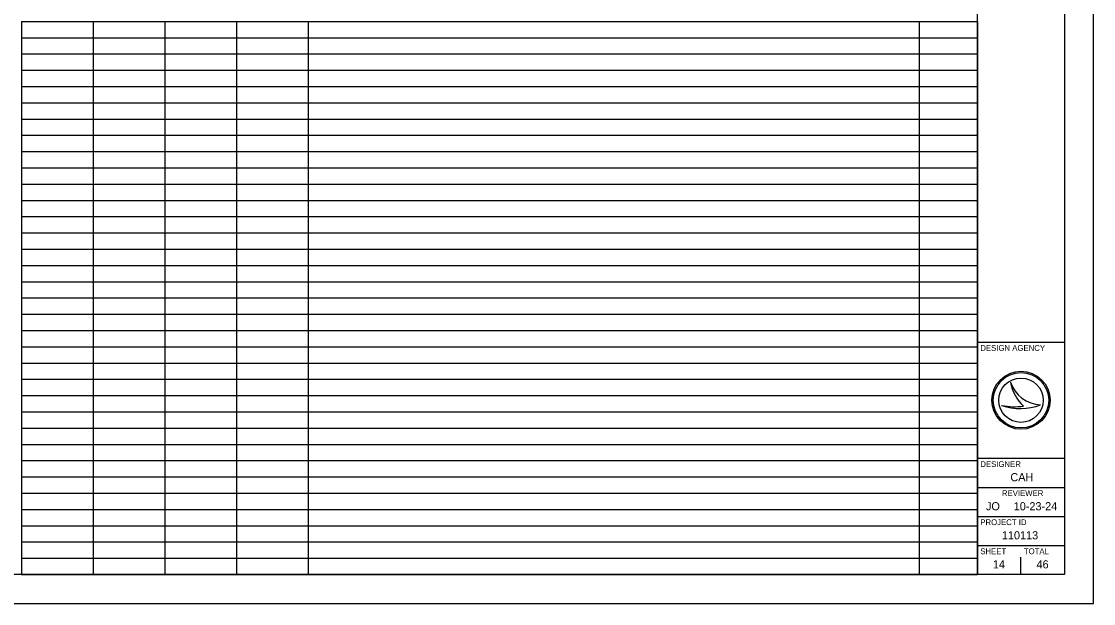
# Model space of a CAD drawing. Extents: x 0 to 34, y 0 to 22.
# Drawn here: x 15.54 to 34, y 0 to 10.02 of the extents above; entities that cross this region are included whole.
import ezdxf

# ---------------------------------------------------------------- set-up
doc = ezdxf.new("R2010")
doc.units = 0
for name, color, linetype in [('SH_Border', 7, 'Continuous'), ('SH_Cut_Line', 7, 'Continuous'), ('SH_Data', 7, 'Continuous'), ('SH_Text', 7, 'Continuous')]:
    doc.layers.add(name, color=color, linetype=linetype)

msp = doc.modelspace()

# ---------------------------------------------------------------- linework, layer by layer
at = {"layer": 'SH_Border'}
for p, q in [((32, 0.5), (32, 21.5)), ((32, 4.5), (33.5, 4.5)), ((32, 2.5), (33.5, 2.5)), ((32, 2), (33.5, 2)), ((32, 1.5), (33.5, 1.5)), ((32, 1), (33.5, 1))]:
    msp.add_line(p, q, dxfattribs=at)
msp.add_lwpolyline([(1.5, 21.5), (33.5, 21.5), (33.5, 0.5), (1.5, 0.5)], close=True, dxfattribs=at)
at = {"layer": 'SH_Cut_Line'}
msp.add_lwpolyline([(0, 0), (34, 0), (34, 22), (0, 22)], close=True, dxfattribs=at)
at = {"layer": 'SH_Data'}
for p, q in [((32.567, 3.81), (32.567, 3.81)), ((32.417, 3.41), (32.417, 3.41)), ((32.75, 3.5), (32.75, 3.5)), ((33.087, 3.419), (33.087, 3.419)), ((32.75, 0.5), (32.75, 0.8)), ((32.375, 0.675), (32.375, 0.675))]:
    msp.add_line(p, q, dxfattribs=at)
for radius in [0.5, 0.477, 0.477, 0.382]:
    msp.add_circle((32.75, 3.5), radius, dxfattribs=at)
for centre, radius, start, end in [((33.116, 3.998), 0.58, 198.9257, 198.9319), ((33.347, 3.97), 0.796, 191.6379, 191.6421), ((33.116, 3.998), 0.58, 198.9319, 267.1657), ((33.347, 3.97), 0.796, 191.6421, 226.0947), ((32.739, 4.37), 1.013, 251.4576, 290.0832), ((32.648, 4.654), 1.266, 259.4964, 259.4995), ((32.739, 4.37), 1.013, 251.4527, 251.4576), ((32.648, 4.654), 1.266, 259.4995, 276.6672)]:
    msp.add_arc(centre, radius, start, end, dxfattribs=at)
at = {"layer": 'SH_Text'}
for p, q in [((15.535, 10.02), (18.003, 10.02)), ((15.535, 10.02), (15.535, 9.74)), ((16.769, 10.02), (16.769, 9.74)), ((18.003, 10.02), (19.237, 10.02)), ((18.003, 10.02), (18.003, 9.74)), ((19.237, 10.02), (32, 10.02)), ((19.237, 10.02), (19.237, 9.74)), ((20.471, 10.02), (20.471, 9.74)), ((30.997, 10.02), (30.997, 9.74)), ((32, 10.02), (32, 9.74)), ((15.535, 9.74), (18.003, 9.74)), ((15.535, 9.74), (15.535, 8.9)), ((16.769, 9.74), (16.769, 8.9)), ((18.003, 9.74), (19.237, 9.74)), ((18.003, 9.74), (18.003, 8.9)), ((19.237, 9.74), (32, 9.74)), ((19.237, 9.74), (19.237, 8.9)), ((20.471, 9.74), (20.471, 8.9)), ((30.997, 9.74), (30.997, 8.9)), ((32, 9.74), (32, 8.9)), ((15.535, 9.46), (18.003, 9.46)), ((18.003, 9.46), (19.237, 9.46)), ((19.237, 9.46), (32, 9.46)), ((15.535, 9.18), (18.003, 9.18)), ((18.003, 9.18), (19.237, 9.18)), ((19.237, 9.18), (32, 9.18)), ((15.535, 8.9), (18.003, 8.9)), ((15.535, 8.9), (15.535, 8.34)), ((16.769, 8.9), (16.769, 8.34)), ((18.003, 8.9), (19.237, 8.9)), ((18.003, 8.9), (18.003, 8.34)), ((19.237, 8.9), (32, 8.9)), ((19.237, 8.9), (19.237, 8.34)), ((20.471, 8.9), (20.471, 8.34)), ((30.997, 8.9), (30.997, 8.34)), ((32, 8.9), (32, 8.34)), ((15.535, 8.62), (18.003, 8.62)), ((18.003, 8.62), (19.237, 8.62)), ((19.237, 8.62), (32, 8.62)), ((15.535, 8.34), (18.003, 8.34)), ((15.535, 8.34), (15.535, 7.5)), ((16.769, 8.34), (16.769, 7.5)), ((18.003, 8.34), (19.237, 8.34)), ((18.003, 8.34), (18.003, 7.5)), ((19.237, 8.34), (32, 8.34)), ((19.237, 8.34), (19.237, 7.5)), ((20.471, 8.34), (20.471, 7.5)), ((30.997, 8.34), (30.997, 7.5)), ((32, 8.34), (32, 7.5)), ((15.535, 8.06), (18.003, 8.06)), ((18.003, 8.06), (19.237, 8.06)), ((19.237, 8.06), (32, 8.06)), ((15.535, 7.78), (18.003, 7.78)), ((18.003, 7.78), (19.237, 7.78)), ((19.237, 7.78), (32, 7.78)), ((15.535, 7.5), (18.003, 7.5)), ((15.535, 7.5), (15.535, 6.94)), ((16.769, 7.5), (16.769, 6.94)), ((18.003, 7.5), (19.237, 7.5)), ((18.003, 7.5), (18.003, 6.94)), ((19.237, 7.5), (32, 7.5)), ((19.237, 7.5), (19.237, 6.94)), ((20.471, 7.5), (20.471, 6.94)), ((30.997, 7.5), (30.997, 6.94)), ((32, 7.5), (32, 6.94)), ((15.535, 7.22), (18.003, 7.22)), ((18.003, 7.22), (19.237, 7.22)), ((19.237, 7.22), (32, 7.22)), ((15.535, 6.94), (18.003, 6.94)), ((15.535, 6.94), (15.535, 6.1)), ((16.769, 6.94), (16.769, 6.1)), ((18.003, 6.94), (19.237, 6.94)), ((18.003, 6.94), (18.003, 6.1)), ((19.237, 6.94), (32, 6.94)), ((19.237, 6.94), (19.237, 6.1)), ((20.471, 6.94), (20.471, 6.1)), ((30.997, 6.94), (30.997, 6.1)), ((32, 6.94), (32, 6.1)), ((15.535, 6.66), (18.003, 6.66)), ((18.003, 6.66), (19.237, 6.66)), ((19.237, 6.66), (32, 6.66)), ((15.535, 6.38), (18.003, 6.38)), ((18.003, 6.38), (19.237, 6.38)), ((19.237, 6.38), (32, 6.38)), ((15.535, 6.1), (18.003, 6.1)), ((15.535, 6.1), (15.535, 4.98)), ((16.769, 6.1), (16.769, 4.98)), ((18.003, 6.1), (19.237, 6.1)), ((18.003, 6.1), (18.003, 4.98)), ((19.237, 6.1), (32, 6.1)), ((19.237, 6.1), (19.237, 4.98)), ((20.471, 6.1), (20.471, 4.98)), ((30.997, 6.1), (30.997, 4.98)), ((32, 6.1), (32, 4.98)), ((15.535, 5.82), (18.003, 5.82)), ((18.003, 5.82), (19.237, 5.82)), ((19.237, 5.82), (32, 5.82)), ((15.535, 5.54), (18.003, 5.54)), ((18.003, 5.54), (19.237, 5.54)), ((19.237, 5.54), (32, 5.54)), ((15.535, 5.26), (18.003, 5.26)), ((18.003, 5.26), (19.237, 5.26)), ((19.237, 5.26), (32, 5.26)), ((15.535, 4.98), (18.003, 4.98)), ((15.535, 4.98), (15.535, 4.7)), ((16.769, 4.98), (16.769, 4.7)), ((18.003, 4.98), (19.237, 4.98)), ((18.003, 4.98), (18.003, 4.7)), ((19.237, 4.98), (32, 4.98)), ((19.237, 4.98), (19.237, 4.7)), ((20.471, 4.98), (20.471, 4.7)), ((30.997, 4.98), (30.997, 4.7)), ((32, 4.98), (32, 4.7)), ((15.535, 4.7), (18.003, 4.7)), ((15.535, 4.7), (15.535, 3.58)), ((16.769, 4.7), (16.769, 3.58)), ((18.003, 4.7), (19.237, 4.7)), ((18.003, 4.7), (18.003, 3.58)), ((19.237, 4.7), (32, 4.7)), ((19.237, 4.7), (19.237, 3.58)), ((20.471, 4.7), (20.471, 3.58)), ((30.997, 4.7), (30.997, 3.58)), ((32, 4.7), (32, 3.58)), ((15.535, 4.42), (18.003, 4.42)), ((18.003, 4.42), (19.237, 4.42)), ((19.237, 4.42), (32, 4.42)), ((15.535, 4.14), (18.003, 4.14)), ((18.003, 4.14), (19.237, 4.14)), ((19.237, 4.14), (32, 4.14)), ((15.535, 3.86), (18.003, 3.86)), ((18.003, 3.86), (19.237, 3.86)), ((19.237, 3.86), (32, 3.86)), ((15.535, 3.58), (18.003, 3.58)), ((15.535, 3.58), (15.535, 3.3)), ((16.769, 3.58), (16.769, 3.3)), ((18.003, 3.58), (19.237, 3.58)), ((18.003, 3.58), (18.003, 3.3)), ((19.237, 3.58), (32, 3.58)), ((19.237, 3.58), (19.237, 3.3)), ((20.471, 3.58), (20.471, 3.3)), ((30.997, 3.58), (30.997, 3.3)), ((32, 3.58), (32, 3.3)), ((15.535, 3.3), (18.003, 3.3)), ((15.535, 3.3), (15.535, 2.18)), ((16.769, 3.3), (16.769, 2.18)), ((18.003, 3.3), (19.237, 3.3)), ((18.003, 3.3), (18.003, 2.18)), ((19.237, 3.3), (32, 3.3)), ((19.237, 3.3), (19.237, 2.18)), ((20.471, 3.3), (20.471, 2.18)), ((30.997, 3.3), (30.997, 2.18)), ((32, 3.3), (32, 2.18)), ((15.535, 3.02), (18.003, 3.02)), ((18.003, 3.02), (19.237, 3.02)), ((19.237, 3.02), (32, 3.02)), ((15.535, 2.74), (18.003, 2.74)), ((18.003, 2.74), (19.237, 2.74)), ((19.237, 2.74), (32, 2.74)), ((15.535, 2.46), (18.003, 2.46)), ((18.003, 2.46), (19.237, 2.46)), ((19.237, 2.46), (32, 2.46)), ((15.535, 2.18), (18.003, 2.18)), ((15.535, 2.18), (15.535, 1.9)), ((16.769, 2.18), (16.769, 1.9)), ((18.003, 2.18), (19.237, 2.18)), ((18.003, 2.18), (18.003, 1.9)), ((19.237, 2.18), (32, 2.18)), ((19.237, 2.18), (19.237, 1.9)), ((20.471, 2.18), (20.471, 1.9)), ((30.997, 2.18), (30.997, 1.9)), ((32, 2.18), (32, 1.9)), ((15.535, 1.9), (18.003, 1.9)), ((15.535, 1.9), (15.535, 0.78)), ((16.769, 1.9), (16.769, 0.78)), ((18.003, 1.9), (19.237, 1.9)), ((18.003, 1.9), (18.003, 0.78)), ((19.237, 1.9), (32, 1.9)), ((19.237, 1.9), (19.237, 0.78)), ((20.471, 1.9), (20.471, 0.78)), ((30.997, 1.9), (30.997, 0.78)), ((32, 1.9), (32, 0.78)), ((15.535, 1.62), (18.003, 1.62)), ((18.003, 1.62), (19.237, 1.62)), ((19.237, 1.62), (32, 1.62)), ((15.535, 1.34), (18.003, 1.34)), ((18.003, 1.34), (19.237, 1.34)), ((19.237, 1.34), (32, 1.34)), ((15.535, 1.06), (18.003, 1.06)), ((18.003, 1.06), (19.237, 1.06)), ((19.237, 1.06), (32, 1.06)), ((15.535, 0.78), (18.003, 0.78)), ((15.535, 0.78), (15.535, 0.5)), ((16.769, 0.78), (16.769, 0.5)), ((18.003, 0.78), (19.237, 0.78)), ((18.003, 0.78), (18.003, 0.5)), ((19.237, 0.78), (32, 0.78)), ((19.237, 0.78), (19.237, 0.5)), ((20.471, 0.78), (20.471, 0.5)), ((30.997, 0.78), (30.997, 0.5)), ((32, 0.78), (32, 0.5)), ((15.535, 0.5), (18.003, 0.5)), ((18.003, 0.5), (19.237, 0.5)), ((19.237, 0.5), (32, 0.5))]:
    msp.add_line(p, q, dxfattribs=at)

# ---------------------------------------------------------------- texts
at = {"layer": 'SH_Data'}
for s, height, p in [('DESIGN AGENCY', 0.1, (32.05, 4.35)), ('DESIGNER', 0.1, (32.05, 2.35)), ('CAH', 0.14, (32.568, 2.105)), ('REVIEWER', 0.1, (32.422, 1.85)), ('JO', 0.14, (32.147, 1.605)), ('10-23-24', 0.14, (32.625, 1.605)), ('PROJECT ID', 0.1, (32.05, 1.35)), ('110113', 0.14, (32.421, 1.105)), ('SHEET', 0.1, (32.05, 0.85)), ('TOTAL', 0.1, (32.8, 0.85)), ('14', 0.14, (32.266, 0.605)), ('46', 0.14, (33.018, 0.605))]:
    msp.add_text(s, height=height, dxfattribs=at).set_placement(p)

doc.saveas('drawing.dxf')
